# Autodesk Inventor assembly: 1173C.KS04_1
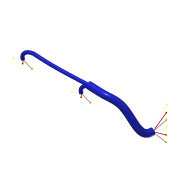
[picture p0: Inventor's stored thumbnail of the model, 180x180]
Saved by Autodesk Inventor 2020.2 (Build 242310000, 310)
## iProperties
Part Number: 1173C.KS04_1
Material: Ogólne
Description: 1173C
Part Number: 1173C.KS03_1
Manager: www.cadconsulting.pl
Company: Fabian Stasiak CAD Consulting
ParentFileIdentifier: 5|1|0|0|62|1|0|0|80|0|65|0|84|0|72|0|83|0|59|0|67|0|58|0|92|0|90|0|98|0|105|0|243|0|114|0|32|0|7|1|119|0|105|0|99|0|122|0|101|0|68|1|32|0|65|0|73|0|32|0|50|0|48
Created: 2014-09
Part Number: W_200_01_P2.Wiązka przewodów2
Document SubType Name: Assembly
Designer: F.Stasiak
Catalog Web Link: www.expertbooks.pl
HarnessSettings: <HarnessSettings><Defaults><Segments><Diameter value="0.200 in" fromwires="True"/><Offset value="0.100 in"/><ColorStyle value="Niebieska - farba ścienna - lśnią
Author: F.Stasiak
Subject: Zbiór ćwiczeń. Autodesk Inventor 2020. Kurs Professional
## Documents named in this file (2)
- C:\2020_Kurs_Professional\R2 Wiązki\W_200_01_P2\AIP\przewody i wiązki przewodów\W_200_01_P2.Wiązka przewodów2.iam
- C:\2020_Kurs_Professional\R2 Wiązki\W_200_01_P2\AIP\przewody i wiązki przewodów\W_200_01_P2.Wiązka przewodów2.ipt
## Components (3 placed, 3 different names)
1. Wiązka przewodów2
2. HA_VC_138:1
3. HA_VC_148:1
